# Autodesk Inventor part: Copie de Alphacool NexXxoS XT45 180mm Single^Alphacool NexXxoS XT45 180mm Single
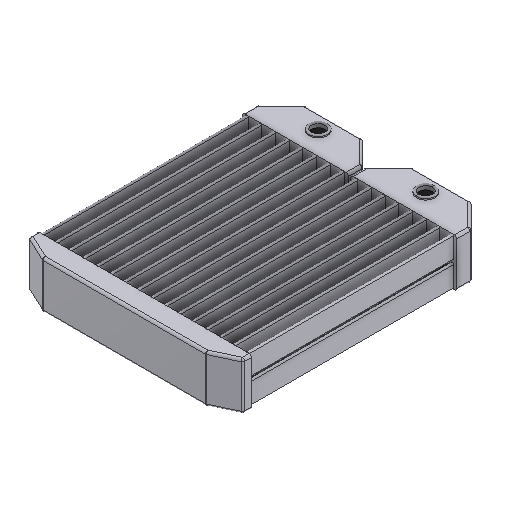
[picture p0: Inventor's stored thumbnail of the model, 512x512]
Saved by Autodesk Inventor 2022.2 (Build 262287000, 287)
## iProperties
Created: 2015-05
Part Number: Copie de Alphacool NexXxoS XT45 180mm Single^Alphacool NexXxoS XT45 180mm Single
Material: Generico
Document SubType Name: Modeling
Designer: 18907419
Density: 1 g/cm^3
Appearance: Default
Author: 18907419
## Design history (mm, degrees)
feature "Solido1"
node "Solido2"
